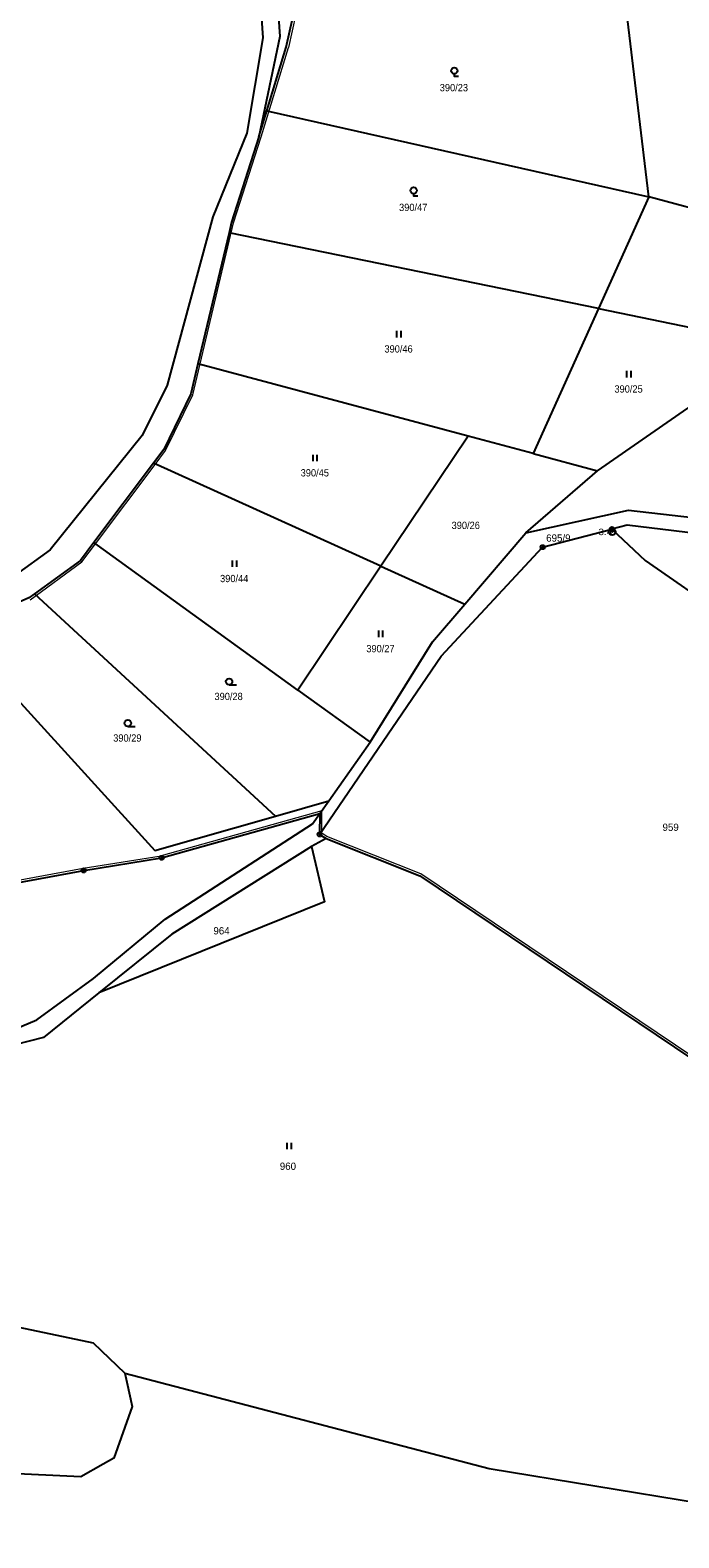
# Model space of a CAD drawing. Extents: x -758887 to -754328, y -1031688 to -1029144.
# Drawn here: x -756855.4 to -756703.8, y -1031001.6 to -1030649.6 of the extents above; entities that cross this region are included whole.
import ezdxf
from ezdxf.enums import TextEntityAlignment as Align

# ---------------------------------------------------------------- set-up
doc = ezdxf.new("R2010")
doc.units = 0
doc.header["$LTSCALE"] = 0.68
for name, color, linetype, lineweight in [('1', 7, 'Continuous', 25), ('3', 7, 'Continuous', 25), ('4', 7, 'Continuous', 13), ('8', 7, 'Continuous', 25)]:
    doc.layers.add(name, color=color, linetype=linetype, lineweight=lineweight)
doc.layers.add('2', color=7, linetype='Continuous')

msp = doc.modelspace()

# ---------------------------------------------------------------- linework, layer by layer
at = {"layer": '1'}
for p, q in [((-756710.9, -1030688.54), (-756716.08, -1030645.06)), ((-756800.1, -1030668.48), (-756710.9, -1030688.54)), ((-756801.95, -1030674.56), (-756808.37, -1030694.48)), ((-756808.37, -1030694.48), (-756808.95, -1030696.93)), ((-756808.95, -1030696.93), (-756816.22, -1030727.49)), ((-756722.65, -1030714.62), (-756808.95, -1030696.93)), ((-756722.65, -1030714.62), (-756737.9, -1030748.45)), ((-756722.65, -1030714.62), (-756677.61, -1030723.85)), ((-756737.9, -1030748.45), (-756753.11, -1030744.38)), ((-756737.9, -1030748.45), (-756722.86, -1030752.48)), ((-756826.6, -1030750.71), (-756840.54, -1030769.25)), ((-756773.49, -1030774.77), (-756826.6, -1030750.71)), ((-756739.59, -1030766.99), (-756722.86, -1030752.48)), ((-756753.87, -1030783.66), (-756739.59, -1030766.99)), ((-756843.68, -1030773.43), (-756854.37, -1030781.22)), ((-756785.64, -1030829.53), (-756776.01, -1030815.89)), ((-756787.76, -1030832.53), (-756785.64, -1030829.53)), ((-756787.76, -1030832.53), (-756787.78, -1030837.41)), ((-756786.29, -1030838.32), (-756789.72, -1030840.25)), ((-756787.78, -1030837.41), (-756786.29, -1030838.32))]:
    msp.add_line(p, q, dxfattribs=at)
for points in [[(-756813.2, -1030609.79), (-756806.23, -1030620.22), (-756802.27, -1030633.34), (-756801.06, -1030651.39), (-756804.83, -1030673.68), (-756812.73, -1030693.17), (-756823.42, -1030732.5), (-756829.21, -1030744.27), (-756850.74, -1030770.98), (-756858.96, -1030776.84), (-756872.42, -1030782.82), (-756888.41, -1030786.68), (-756900.83, -1030788.9), (-756918.58, -1030789.61), (-756949.69, -1030787.03)], [(-756798.32, -1030632.84), (-756797.07, -1030651.12), (-756801.95, -1030674.56), (-756800.1, -1030668.48)], [(-756800.1, -1030668.48), (-756795.57, -1030653.56), (-756791.78, -1030636.51)], [(-756677.61, -1030723.85), (-756693.48, -1030693.18), (-756710.9, -1030688.54), (-756722.65, -1030714.62)], [(-756722.86, -1030752.48), (-756701.77, -1030737.88), (-756677.61, -1030723.85)], [(-756753.11, -1030744.38), (-756816.22, -1030727.49), (-756817.9, -1030734.56)], [(-756817.9, -1030734.56), (-756824.2, -1030747.52), (-756826.6, -1030750.71)], [(-756753.11, -1030744.38), (-756773.49, -1030774.77), (-756753.87, -1030783.66)], [(-756739.59, -1030766.99), (-756715.62, -1030761.72), (-756670.06, -1030766.9), (-756666.74, -1030766.79)], [(-756787.78, -1030837.41), (-756759.38, -1030795.79), (-756735.67, -1030770.33), (-756719.48, -1030766.11)], [(-756656.98, -1030770.25), (-756674.86, -1030770.19), (-756715.94, -1030765.19), (-756719.48, -1030766.11)], [(-756719.48, -1030766.11), (-756711.75, -1030773.45), (-756693.09, -1030786.36), (-756660.88, -1030799.59), (-756660.11, -1030793.78)], [(-756792.89, -1030803.69), (-756840.54, -1030769.25), (-756843.68, -1030773.43)], [(-756773.49, -1030774.77), (-756792.89, -1030803.69), (-756776.01, -1030815.89)], [(-756854.37, -1030781.22), (-756855.7, -1030782.19), (-756870.69, -1030788.81), (-756873.32, -1030789.58)], [(-756854.37, -1030781.22), (-756798.12, -1030833.1), (-756785.64, -1030829.53)], [(-756776.01, -1030815.89), (-756761.4, -1030792.45), (-756753.87, -1030783.66)], [(-756873.32, -1030789.58), (-756826.28, -1030841.14), (-756798.12, -1030833.1)], [(-756917, -1030854.23), (-756884.29, -1030878.99), (-756867.82, -1030883.81), (-756860.32, -1030883.4), (-756853.86, -1030880.71), (-756840.65, -1030871.04), (-756823.86, -1030857.21), (-756789.42, -1030834.89), (-756787.76, -1030832.53)], [(-756897.85, -1030855.91), (-756842.91, -1030845.79), (-756824.71, -1030842.86), (-756787.76, -1030832.53)], [(-756789.72, -1030840.25), (-756786.64, -1030853.12), (-756839.38, -1030874.35)], [(-756789.72, -1030840.25), (-756822.32, -1030860.66), (-756839.38, -1030874.35)], [(-756786.29, -1030838.32), (-756764.35, -1030847.07), (-756692.05, -1030895.68), (-756672.17, -1030908.07)], [(-756839.38, -1030874.35), (-756852.29, -1030884.82), (-756866.11, -1030888.3), (-756882.18, -1030884.5)], [(-756925.07, -1030938.35), (-756840.68, -1030956.07), (-756833.28, -1030963.17)], [(-756833.28, -1030963.17), (-756832.82, -1030965.27), (-756831.58, -1030970.94), (-756835.83, -1030983.04), (-756838.36, -1030984.46), (-756843.55, -1030987.38), (-756861.62, -1030986.52), (-756871.57, -1030986.44), (-756880.1, -1030986.37), (-756900.79, -1030986.48), (-756925.29, -1030987.43), (-756939, -1030991.92), (-756948.79, -1030997.61)], [(-756833.28, -1030963.17), (-756748.2, -1030985.46), (-756649.43, -1031001.63)]]:
    msp.add_lwpolyline(points, dxfattribs=at)
at = {"layer": '3'}
for p, q in [((-756769.751, -1030721.34), (-756769.751, -1030719.84)), ((-756768.75, -1030721.34), (-756768.75, -1030719.84)), ((-756716.011, -1030730.69), (-756716.011, -1030729.19)), ((-756715.01, -1030730.69), (-756715.01, -1030729.19)), ((-756789.321, -1030750.27), (-756789.321, -1030748.77)), ((-756788.32, -1030750.27), (-756788.32, -1030748.77)), ((-756808.151, -1030774.95), (-756808.151, -1030773.45)), ((-756807.15, -1030774.95), (-756807.15, -1030773.45)), ((-756773.981, -1030791.32), (-756773.981, -1030789.82)), ((-756772.98, -1030791.32), (-756772.98, -1030789.82)), ((-756808.933, -1030802.48), (-756807.183, -1030802.48)), ((-756832.603, -1030812.18), (-756830.853, -1030812.18)), ((-756795.361, -1030910.92), (-756795.361, -1030909.42)), ((-756794.36, -1030910.92), (-756794.36, -1030909.42))]:
    msp.add_line(p, q, dxfattribs=at)
for points in [[(-756756.31, -1030659.842), (-756756.31, -1030660.34), (-756755.309, -1030660.34)], [(-756765.82, -1030687.802), (-756765.82, -1030688.3), (-756764.819, -1030688.3)]]:
    msp.add_lwpolyline(points, dxfattribs=at)
for centre in [(-756756.3093, -1030659.0909), (-756765.8193, -1030687.0509), (-756808.9329, -1030801.7298), (-756832.6029, -1030811.4298)]:
    msp.add_circle(centre, 0.75, dxfattribs=at)
at = {"layer": '4'}
for p, q in [((-756790.79, -1030634.36), (-756795.08, -1030653.68)), ((-756801.41, -1030674.52), (-756795.08, -1030653.68)), ((-756807.89, -1030694.61), (-756801.41, -1030674.52)), ((-756817.43, -1030734.73), (-756807.89, -1030694.61)), ((-756855.4, -1030782.59), (-756843.31, -1030773.77))]:
    msp.add_line(p, q, dxfattribs=at)
for points in [[(-756843.31, -1030773.77), (-756840.14, -1030769.55), (-756826.2, -1030751.01), (-756823.77, -1030747.78), (-756817.43, -1030734.73)], [(-756660.54, -1030793.25), (-756661.38, -1030799.52), (-756662.1, -1030804.97), (-756620.96, -1030811.05), (-756615.29, -1030811.9), (-756627.35, -1030838.46), (-756661.14, -1030891.35), (-756672.31, -1030907.39), (-756691.78, -1030895.26), (-756764.12, -1030846.63), (-756786.07, -1030837.87), (-756787.28, -1030837.13)], [(-756787.28, -1030837.13), (-756787.26, -1030831.87), (-756824.82, -1030842.37)], [(-756938.49, -1030847.57), (-756916.91, -1030853.74), (-756897.87, -1030855.41), (-756843, -1030845.3), (-756824.82, -1030842.37)]]:
    msp.add_lwpolyline(points, dxfattribs=at)
at = {"layer": '8'}
for centre, radius in [((-756719.44, -1030766.7698), 0.75), ((-756719.48, -1030766.1099), 0.5), ((-756719.48, -1030766.1099), 0.0303), ((-756735.67, -1030770.3299), 0.5), ((-756719.44, -1030766.7698), 0.03), ((-756735.67, -1030770.3299), 0.0303), ((-756787.78, -1030837.4099), 0.5), ((-756787.78, -1030837.4099), 0.0303), ((-756824.71, -1030842.8599), 0.5), ((-756824.71, -1030842.8599), 0.0303), ((-756842.91, -1030845.7899), 0.5), ((-756842.91, -1030845.7899), 0.0303)]:
    msp.add_circle(centre, radius, dxfattribs=at)

# ---------------------------------------------------------------- texts
at = {"layer": '2', "width": 0.95}
for s, p in [('390/23', (-756756.409, -1030663.89)), ('390/47', (-756765.919, -1030691.85)), ('390/46', (-756769.339, -1030724.89)), ('390/25', (-756715.599, -1030734.24)), ('390/45', (-756788.909, -1030753.82)), ('390/26', (-756753.639, -1030766.09)), ('390/44', (-756807.739, -1030778.5)), ('390/27', (-756773.569, -1030794.87)), ('390/28', (-756809.049, -1030806.03)), ('390/29', (-756832.709, -1030815.73))]:
    msp.add_text(s, height=1.7, dxfattribs=at).set_placement(p, align=Align.CENTER)
at = {"layer": '2'}
for s, p in [('695/9', (-756732, -1030769.05)), ('959', (-756705.769, -1030836.576)), ('964', (-756810.709, -1030860.746)), ('960', (-756795.189, -1030915.716))]:
    msp.add_text(s, height=1.7, dxfattribs=at).set_placement(p, align=Align.CENTER)
at = {"layer": '8', "width": 1.15}
msp.add_text('3.4', height=1.5, dxfattribs=at).set_placement((-756719.439, -1030767.52), align=Align.RIGHT)

doc.saveas('drawing.dxf')
